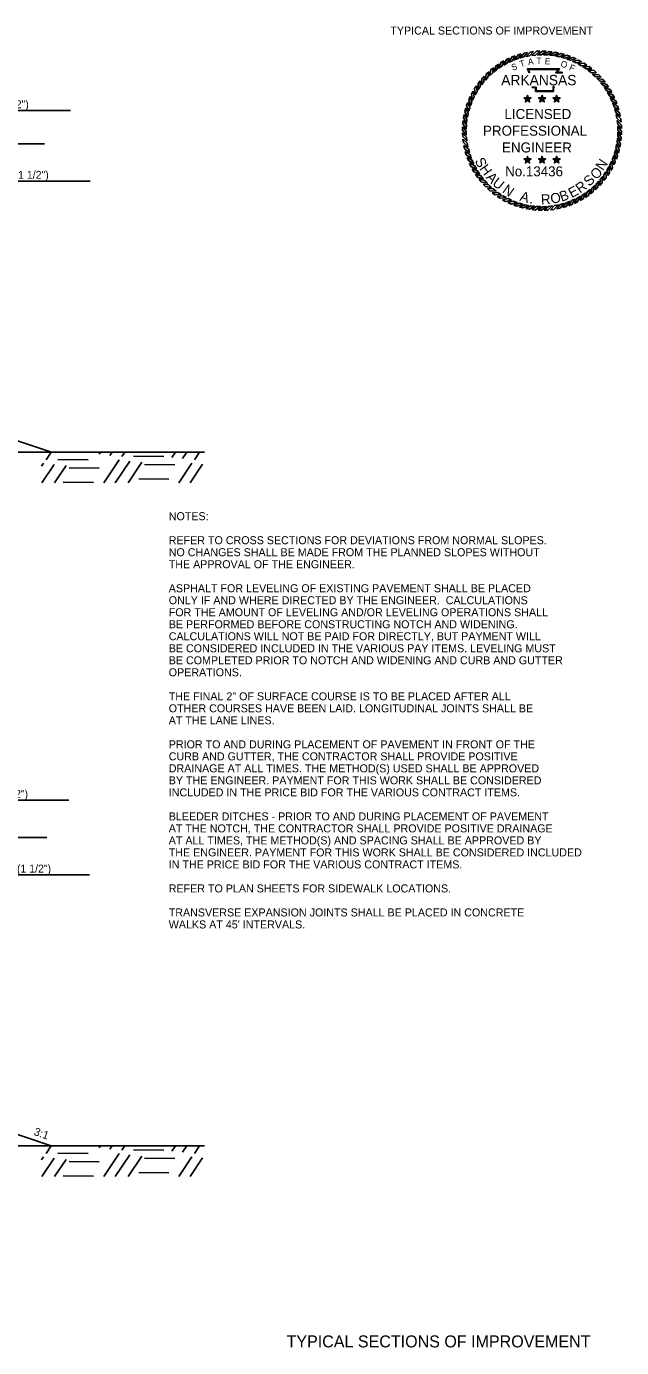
# Model space of a CAD drawing. Extents: x 1001270 to 1003428, y 1840152 to 1842912.
# Drawn here: x 1001904.5 to 1001949.2, y 1841962.9 to 1842061.9 of the extents above; entities that cross this region are included whole.
import ezdxf

# ---------------------------------------------------------------- set-up
doc = ezdxf.new("R2010")
doc.units = 0
for name, color, linetype in [('1', 7, 'Continuous'), ('19', 7, 'Continuous'), ('60', 7, 'Continuous'), ('G-ANNO-SYMB', 7, 'Continuous')]:
    doc.layers.add(name, color=color, linetype=linetype)

msp = doc.modelspace()

# ---------------------------------------------------------------- linework, layer by layer
at = {"layer": '19'}
for p, q in [((1001891.195, 1842055.58), (1001907.836, 1842055.58)), ((1001891.195, 1842053.086), (1001905.889, 1842053.086)), ((1001893.694, 1842050.286), (1001909.309, 1842050.286)), ((1001905.996, 1842029.386), (1001906.388, 1842029.969)), ((1001909.982, 1842029.82), (1001910.087, 1842029.97)), ((1001910.776, 1842029.729), (1001910.942, 1842029.973)), ((1001911.672, 1842029.636), (1001911.897, 1842029.975)), ((1001912.559, 1842029.666), (1001914.82, 1842029.654)), ((1001915.436, 1842029.581), (1001915.698, 1842029.976)), ((1001916.23, 1842029.489), (1001916.562, 1842029.978)), ((1001917.126, 1842029.397), (1001917.507, 1842029.971)), ((1001905.657, 1842028.918), (1001905.81, 1842029.144)), ((1001905.679, 1842027.67), (1001906.605, 1842029.052)), ((1001906.634, 1842027.672), (1001907.5, 1842028.96)), ((1001906.885, 1842029.425), (1001909.145, 1842029.404)), ((1001907.725, 1842028.796), (1001909.985, 1842028.775)), ((1001910.334, 1842027.673), (1001911.486, 1842029.394)), ((1001911.188, 1842027.676), (1001912.281, 1842029.302)), ((1001912.144, 1842027.678), (1001913.176, 1842029.21)), ((1001913.389, 1842029.037), (1001915.66, 1842029.025)), ((1001915.944, 1842027.679), (1001916.94, 1842029.155)), ((1001916.798, 1842027.681), (1001917.735, 1842029.063)), ((1001907.272, 1842027.717), (1001909.543, 1842027.704)), ((1001912.947, 1842027.967), (1001915.207, 1842027.946)), ((1001891.195, 1842003.888), (1001907.696, 1842003.888)), ((1001891.195, 1842001.088), (1001906.057, 1842001.088)), ((1001893.694, 1841998.288), (1001909.258, 1841998.288)), ((1001906.388, 1841977.971), (1001897.697, 1841980.868)), ((1001905.996, 1841977.388), (1001906.388, 1841977.971)), ((1001909.982, 1841977.822), (1001910.087, 1841977.972)), ((1001910.776, 1841977.73), (1001910.942, 1841977.975)), ((1001911.672, 1841977.638), (1001911.897, 1841977.977)), ((1001915.436, 1841977.583), (1001915.698, 1841977.978)), ((1001916.23, 1841977.491), (1001916.562, 1841977.979)), ((1001917.126, 1841977.399), (1001917.507, 1841977.973)), ((1001905.657, 1841976.92), (1001905.81, 1841977.146)), ((1001905.679, 1841975.671), (1001906.605, 1841977.054)), ((1001906.634, 1841975.674), (1001907.5, 1841976.962)), ((1001906.885, 1841977.427), (1001909.145, 1841977.406)), ((1001910.334, 1841975.675), (1001911.486, 1841977.396)), ((1001911.188, 1841975.677), (1001912.281, 1841977.304)), ((1001912.144, 1841975.68), (1001913.176, 1841977.212)), ((1001912.559, 1841977.668), (1001914.82, 1841977.656)), ((1001913.389, 1841977.039), (1001915.66, 1841977.027)), ((1001915.944, 1841975.681), (1001916.94, 1841977.156)), ((1001916.798, 1841975.683), (1001917.735, 1841977.065)), ((1001907.725, 1841976.798), (1001909.985, 1841976.776)), ((1001907.272, 1841975.719), (1001909.543, 1841975.706)), ((1001912.947, 1841975.969), (1001915.207, 1841975.947))]:
    msp.add_line(p, q, dxfattribs=at)
for points in [[(1001906.395, 1842029.969), (1001897.704, 1842032.866), (1001889.707, 1842032.706)], [(1001887.878, 1842031.719), (1001896.643, 1842030.165), (1001897.635, 1842029.97), (1001917.886, 1842029.968)], [(1001887.878, 1841979.721), (1001896.643, 1841978.167), (1001897.635, 1841977.972), (1001917.886, 1841977.97)]]:
    msp.add_lwpolyline(points, dxfattribs=at)
at = {"layer": 'G-ANNO-SYMB'}
for points in [[(1001940.336, 1842059.301), (1001940.114, 1842059.173), (1001939.954, 1842058.744), (1001940.185, 1842058.897)], [(1001940.756, 1842059.509), (1001940.524, 1842059.399), (1001940.331, 1842058.984), (1001940.574, 1842059.118)], [(1001941.191, 1842059.683), (1001940.951, 1842059.592), (1001940.726, 1842059.194), (1001940.978, 1842059.308)], [(1001941.638, 1842059.823), (1001941.392, 1842059.751), (1001941.136, 1842059.372), (1001941.397, 1842059.466)], [(1001942.094, 1842059.928), (1001941.843, 1842059.875), (1001941.559, 1842059.517), (1001941.826, 1842059.59)], [(1001942.558, 1842059.996), (1001942.303, 1842059.963), (1001941.992, 1842059.629), (1001942.264, 1842059.681)], [(1001943.025, 1842060.028), (1001942.769, 1842060.015), (1001942.432, 1842059.706), (1001942.707, 1842059.737)], [(1001943.494, 1842060.023), (1001943.237, 1842060.03), (1001942.877, 1842059.749), (1001943.154, 1842059.757)], [(1001943.96, 1842059.981), (1001943.705, 1842060.009), (1001943.324, 1842059.756), (1001943.601, 1842059.743)], [(1001944.422, 1842059.903), (1001944.17, 1842059.95), (1001943.77, 1842059.729), (1001944.045, 1842059.694)], [(1001944.876, 1842059.789), (1001944.629, 1842059.856), (1001944.213, 1842059.666), (1001944.484, 1842059.61)], [(1001945.32, 1842059.639), (1001945.079, 1842059.725), (1001944.649, 1842059.569), (1001944.915, 1842059.492)], [(1001945.751, 1842059.455), (1001945.517, 1842059.56), (1001945.076, 1842059.438), (1001945.336, 1842059.34)], [(1001946.166, 1842059.238), (1001945.941, 1842059.361), (1001945.492, 1842059.274), (1001945.743, 1842059.156)], [(1001939.193, 1842058.488), (1001939.007, 1842058.312), (1001938.951, 1842057.858), (1001939.141, 1842058.06)], [(1001939.553, 1842058.789), (1001939.353, 1842058.628), (1001939.262, 1842058.18), (1001939.467, 1842058.366)], [(1001939.934, 1842059.06), (1001939.723, 1842058.915), (1001939.597, 1842058.476), (1001939.816, 1842058.646)], [(1001946.563, 1842058.989), (1001946.348, 1842059.129), (1001945.894, 1842059.078), (1001946.135, 1842058.94)], [(1001946.939, 1842058.71), (1001946.736, 1842058.866), (1001946.279, 1842058.851), (1001946.508, 1842058.695)], [(1001947.292, 1842058.402), (1001947.102, 1842058.574), (1001946.645, 1842058.594), (1001946.861, 1842058.421)], [(1001947.62, 1842058.067), (1001947.444, 1842058.254), (1001946.99, 1842058.309), (1001947.192, 1842058.12)], [(1001938.271, 1842057.432), (1001938.131, 1842057.217), (1001938.182, 1842056.763), (1001938.32, 1842057.003)], [(1001938.55, 1842057.808), (1001938.394, 1842057.605), (1001938.41, 1842057.148), (1001938.565, 1842057.377)], [(1001938.858, 1842058.161), (1001938.686, 1842057.97), (1001938.666, 1842057.514), (1001938.84, 1842057.73)], [(1001947.92, 1842057.708), (1001947.759, 1842057.907), (1001947.311, 1842057.999), (1001947.498, 1842057.794)], [(1001948.191, 1842057.326), (1001948.047, 1842057.537), (1001947.607, 1842057.664), (1001947.777, 1842057.445)], [(1001948.432, 1842056.924), (1001948.304, 1842057.146), (1001947.876, 1842057.306), (1001948.028, 1842057.075)], [(1001937.621, 1842056.189), (1001937.535, 1842055.947), (1001937.691, 1842055.518), (1001937.768, 1842055.784)], [(1001937.805, 1842056.62), (1001937.7, 1842056.386), (1001937.822, 1842055.945), (1001937.92, 1842056.204)], [(1001938.022, 1842057.035), (1001937.899, 1842056.81), (1001937.986, 1842056.361), (1001938.104, 1842056.612)], [(1001942.105, 1842056.44), (1001942.044, 1842056.524), (1001941.845, 1842056.524), (1001942.006, 1842056.408)], [(1001942.105, 1842056.44), (1001942.006, 1842056.408), (1001941.945, 1842056.219), (1001942.105, 1842056.336)], [(1001942.105, 1842056.44), (1001942.166, 1842056.524), (1001942.105, 1842056.713), (1001942.044, 1842056.524)], [(1001942.105, 1842056.44), (1001942.204, 1842056.408), (1001942.364, 1842056.524), (1001942.166, 1842056.524)], [(1001942.105, 1842056.44), (1001942.105, 1842056.336), (1001942.265, 1842056.219), (1001942.204, 1842056.408)], [(1001943.196, 1842056.44), (1001943.135, 1842056.524), (1001942.936, 1842056.524), (1001943.097, 1842056.408)], [(1001943.196, 1842056.44), (1001943.097, 1842056.408), (1001943.035, 1842056.219), (1001943.196, 1842056.336)], [(1001943.196, 1842056.44), (1001943.257, 1842056.524), (1001943.196, 1842056.713), (1001943.135, 1842056.524)], [(1001943.196, 1842056.44), (1001943.295, 1842056.408), (1001943.455, 1842056.524), (1001943.257, 1842056.524)], [(1001943.196, 1842056.44), (1001943.196, 1842056.336), (1001943.356, 1842056.219), (1001943.295, 1842056.408)], [(1001944.287, 1842056.44), (1001944.225, 1842056.524), (1001944.027, 1842056.524), (1001944.188, 1842056.408)], [(1001944.287, 1842056.44), (1001944.188, 1842056.408), (1001944.126, 1842056.219), (1001944.287, 1842056.336)], [(1001944.287, 1842056.44), (1001944.348, 1842056.524), (1001944.287, 1842056.713), (1001944.225, 1842056.524)], [(1001944.287, 1842056.44), (1001944.386, 1842056.408), (1001944.546, 1842056.524), (1001944.348, 1842056.524)], [(1001944.287, 1842056.44), (1001944.287, 1842056.336), (1001944.447, 1842056.219), (1001944.386, 1842056.408)], [(1001948.64, 1842056.504), (1001948.53, 1842056.736), (1001948.116, 1842056.929), (1001948.249, 1842056.686)], [(1001948.815, 1842056.069), (1001948.723, 1842056.309), (1001948.325, 1842056.534), (1001948.439, 1842056.282)], [(1001937.357, 1842055.291), (1001937.31, 1842055.039), (1001937.532, 1842054.639), (1001937.566, 1842054.914)], [(1001937.471, 1842055.745), (1001937.404, 1842055.497), (1001937.594, 1842055.081), (1001937.65, 1842055.353)], [(1001948.955, 1842055.622), (1001948.882, 1842055.869), (1001948.503, 1842056.124), (1001948.597, 1842055.863)], [(1001949.059, 1842055.166), (1001949.006, 1842055.417), (1001948.649, 1842055.701), (1001948.722, 1842055.434)], [(1001949.127, 1842054.702), (1001949.095, 1842054.957), (1001948.76, 1842055.269), (1001948.812, 1842054.996)], [(1001937.237, 1842054.362), (1001937.23, 1842054.106), (1001937.511, 1842053.746), (1001937.503, 1842054.023)], [(1001937.279, 1842054.829), (1001937.252, 1842054.574), (1001937.504, 1842054.193), (1001937.517, 1842054.469)], [(1001949.159, 1842054.235), (1001949.146, 1842054.491), (1001948.837, 1842054.828), (1001948.868, 1842054.553)], [(1001949.154, 1842053.767), (1001949.162, 1842054.023), (1001948.88, 1842054.383), (1001948.889, 1842054.106)], [(1001937.232, 1842053.894), (1001937.245, 1842053.638), (1001937.554, 1842053.301), (1001937.524, 1842053.576)], [(1001937.264, 1842053.427), (1001937.297, 1842053.172), (1001937.631, 1842052.86), (1001937.579, 1842053.132)], [(1001949.034, 1842052.838), (1001949.082, 1842053.09), (1001948.86, 1842053.49), (1001948.825, 1842053.215)], [(1001949.113, 1842053.3), (1001949.14, 1842053.555), (1001948.888, 1842053.936), (1001948.875, 1842053.659)], [(1001937.332, 1842052.963), (1001937.385, 1842052.712), (1001937.743, 1842052.427), (1001937.67, 1842052.695)], [(1001937.437, 1842052.506), (1001937.509, 1842052.26), (1001937.888, 1842052.005), (1001937.794, 1842052.265)], [(1001948.771, 1842051.94), (1001948.857, 1842052.181), (1001948.7, 1842052.611), (1001948.623, 1842052.345)], [(1001948.92, 1842052.384), (1001948.987, 1842052.631), (1001948.797, 1842053.048), (1001948.741, 1842052.776)], [(1001937.577, 1842052.059), (1001937.668, 1842051.82), (1001938.066, 1842051.595), (1001937.952, 1842051.847)], [(1001937.751, 1842051.625), (1001937.861, 1842051.393), (1001938.276, 1842051.2), (1001938.142, 1842051.443)], [(1001942.105, 1842051.872), (1001942.044, 1842051.956), (1001941.845, 1842051.956), (1001942.006, 1842051.84)], [(1001942.105, 1842051.872), (1001942.006, 1842051.84), (1001941.945, 1842051.651), (1001942.105, 1842051.768)], [(1001942.105, 1842051.872), (1001942.166, 1842051.956), (1001942.105, 1842052.145), (1001942.044, 1842051.956)], [(1001942.105, 1842051.872), (1001942.204, 1842051.84), (1001942.364, 1842051.956), (1001942.166, 1842051.956)], [(1001942.105, 1842051.872), (1001942.105, 1842051.768), (1001942.265, 1842051.651), (1001942.204, 1842051.84)], [(1001943.196, 1842051.872), (1001943.135, 1842051.956), (1001942.936, 1842051.956), (1001943.097, 1842051.84)], [(1001943.196, 1842051.872), (1001943.097, 1842051.84), (1001943.035, 1842051.651), (1001943.196, 1842051.768)], [(1001943.196, 1842051.872), (1001943.257, 1842051.956), (1001943.196, 1842052.145), (1001943.135, 1842051.956)], [(1001943.196, 1842051.872), (1001943.295, 1842051.84), (1001943.455, 1842051.956), (1001943.257, 1842051.956)], [(1001943.196, 1842051.872), (1001943.196, 1842051.768), (1001943.356, 1842051.651), (1001943.295, 1842051.84)], [(1001944.287, 1842051.872), (1001944.225, 1842051.956), (1001944.027, 1842051.956), (1001944.188, 1842051.84)], [(1001944.287, 1842051.872), (1001944.188, 1842051.84), (1001944.126, 1842051.651), (1001944.287, 1842051.768)], [(1001944.287, 1842051.872), (1001944.348, 1842051.956), (1001944.287, 1842052.145), (1001944.225, 1842051.956)], [(1001944.287, 1842051.872), (1001944.386, 1842051.84), (1001944.546, 1842051.956), (1001944.348, 1842051.956)], [(1001944.287, 1842051.872), (1001944.287, 1842051.768), (1001944.447, 1842051.651), (1001944.386, 1842051.84)], [(1001948.121, 1842050.697), (1001948.261, 1842050.912), (1001948.209, 1842051.366), (1001948.072, 1842051.125)], [(1001948.37, 1842051.094), (1001948.492, 1842051.319), (1001948.405, 1842051.768), (1001948.287, 1842051.517)], [(1001948.587, 1842051.509), (1001948.692, 1842051.743), (1001948.569, 1842052.184), (1001948.471, 1842051.924)], [(1001937.96, 1842051.205), (1001938.087, 1842050.983), (1001938.516, 1842050.822), (1001938.363, 1842051.054)], [(1001938.2, 1842050.803), (1001938.345, 1842050.591), (1001938.785, 1842050.465), (1001938.615, 1842050.684)], [(1001938.471, 1842050.421), (1001938.632, 1842050.221), (1001939.08, 1842050.13), (1001938.894, 1842050.335)], [(1001947.198, 1842049.64), (1001947.385, 1842049.817), (1001947.441, 1842050.27), (1001947.251, 1842050.068)], [(1001947.533, 1842049.968), (1001947.705, 1842050.158), (1001947.725, 1842050.615), (1001947.552, 1842050.399)], [(1001947.841, 1842050.321), (1001947.998, 1842050.524), (1001947.982, 1842050.981), (1001947.826, 1842050.752)], [(1001938.772, 1842050.062), (1001938.948, 1842049.875), (1001939.402, 1842049.82), (1001939.2, 1842050.009)], [(1001939.099, 1842049.727), (1001939.29, 1842049.555), (1001939.747, 1842049.535), (1001939.53, 1842049.708)], [(1001939.452, 1842049.419), (1001939.656, 1842049.262), (1001940.113, 1842049.278), (1001939.883, 1842049.434)], [(1001946.055, 1842048.828), (1001946.278, 1842048.956), (1001946.438, 1842049.384), (1001946.206, 1842049.232)], [(1001946.457, 1842049.069), (1001946.669, 1842049.214), (1001946.795, 1842049.653), (1001946.576, 1842049.483)], [(1001946.839, 1842049.34), (1001947.039, 1842049.501), (1001947.13, 1842049.949), (1001946.925, 1842049.763)], [(1001939.828, 1842049.14), (1001940.043, 1842048.999), (1001940.498, 1842049.051), (1001940.257, 1842049.188)], [(1001940.225, 1842048.891), (1001940.45, 1842048.768), (1001940.899, 1842048.855), (1001940.648, 1842048.973)], [(1001940.64, 1842048.673), (1001940.874, 1842048.569), (1001941.315, 1842048.691), (1001941.056, 1842048.789)], [(1001941.071, 1842048.49), (1001941.313, 1842048.403), (1001941.742, 1842048.56), (1001941.476, 1842048.637)], [(1001941.515, 1842048.34), (1001941.763, 1842048.273), (1001942.179, 1842048.463), (1001941.907, 1842048.519)], [(1001941.969, 1842048.226), (1001942.222, 1842048.179), (1001942.621, 1842048.4), (1001942.346, 1842048.435)], [(1001942.431, 1842048.148), (1001942.686, 1842048.12), (1001943.068, 1842048.373), (1001942.791, 1842048.386)], [(1001942.898, 1842048.106), (1001943.154, 1842048.099), (1001943.515, 1842048.38), (1001943.238, 1842048.371)], [(1001943.366, 1842048.101), (1001943.622, 1842048.114), (1001943.96, 1842048.423), (1001943.684, 1842048.392)], [(1001943.834, 1842048.133), (1001944.088, 1842048.166), (1001944.4, 1842048.5), (1001944.128, 1842048.448)], [(1001944.297, 1842048.201), (1001944.548, 1842048.254), (1001944.833, 1842048.612), (1001944.565, 1842048.538)], [(1001944.754, 1842048.305), (1001945, 1842048.378), (1001945.256, 1842048.757), (1001944.995, 1842048.663)], [(1001945.201, 1842048.445), (1001945.44, 1842048.537), (1001945.666, 1842048.935), (1001945.413, 1842048.821)], [(1001945.635, 1842048.62), (1001945.867, 1842048.73), (1001946.06, 1842049.144), (1001945.818, 1842049.011)]]:
    msp.add_lwpolyline(points, close=True, dxfattribs=at)
for points in [[(1001942.24, 1842058.394), (1001942.101, 1842058.696), (1001944.507, 1842058.697), (1001944.306, 1842058.444), (1001944.47, 1842058.447), (1001944.606, 1842058.448), (1001944.743, 1842058.433)], [(1001942.275, 1842058.41), (1001942.16, 1842058.657), (1001944.428, 1842058.659), (1001944.226, 1842058.405), (1001944.47, 1842058.408), (1001944.604, 1842058.41), (1001944.739, 1842058.396)], [(1001944.128, 1842057.386), (1001944.087, 1842057.353), (1001944.073, 1842057.303), (1001944.06, 1842057.178), (1001944.06, 1842057.012), (1001942.716, 1842057.012), (1001942.716, 1842057.236), (1001942.716, 1842057.286), (1001942.662, 1842057.303), (1001942.471, 1842057.303), (1001942.437, 1842057.354)], [(1001944.104, 1842057.416), (1001944.053, 1842057.374), (1001944.036, 1842057.31), (1001944.022, 1842057.18), (1001944.022, 1842057.05), (1001942.755, 1842057.05), (1001942.755, 1842057.236), (1001942.755, 1842057.314), (1001942.668, 1842057.341), (1001942.491, 1842057.341), (1001942.469, 1842057.375)]]:
    msp.add_lwpolyline(points, dxfattribs=at)

# ---------------------------------------------------------------- texts
at = {"layer": '1'}
msp.add_text('TYPICAL SECTIONS OF IMPROVEMENT', height=0.6, dxfattribs=at).set_placement((1001931.816, 1842061.273))
at = {"layer": '19'}
for s, height, p in [('7\'-0" AVG. ACHM SURFACE COURSE (1/2")', 0.59001, (1001888.778, 1842055.754)), ('9\'-6" AVG. ACHM BASE COURSE (1 1/2")', 0.59001, (1001891.281, 1842050.461)), ('NOTES:', 0.6, (1001915.198, 1842024.869)), ('REFER TO CROSS SECTIONS FOR DEVIATIONS FROM NORMAL SLOPES.', 0.6, (1001915.198, 1842023.069)), ('NO CHANGES SHALL BE MADE FROM THE PLANNED SLOPES WITHOUT', 0.6, (1001915.198, 1842022.169)), ('THE APPROVAL OF THE ENGINEER.', 0.6, (1001915.198, 1842021.269)), ('ASPHALT FOR LEVELING OF EXISTING PAVEMENT SHALL BE PLACED', 0.6, (1001915.198, 1842019.469)), ('ONLY IF AND WHERE DIRECTED BY THE ENGINEER.  CALCULATIONS', 0.6, (1001915.198, 1842018.569)), ('FOR THE AMOUNT OF LEVELING AND/OR LEVELING OPERATIONS SHALL', 0.6, (1001915.198, 1842017.669)), ('BE PERFORMED BEFORE CONSTRUCTING NOTCH AND WIDENING.', 0.6, (1001915.198, 1842016.769)), ('CALCULATIONS WILL NOT BE PAID FOR DIRECTLY, BUT PAYMENT WILL', 0.6, (1001915.198, 1842015.869)), ('BE CONSIDERED INCLUDED IN THE VARIOUS PAY ITEMS. LEVELING MUST ', 0.6, (1001915.198, 1842014.969)), ('BE COMPLETED PRIOR TO NOTCH AND WIDENING AND CURB AND GUTTER', 0.6, (1001915.198, 1842014.069)), ('OPERATIONS. ', 0.6, (1001915.198, 1842013.169)), ('THE FINAL 2" OF SURFACE COURSE IS TO BE PLACED AFTER ALL', 0.6, (1001915.198, 1842011.369)), ('OTHER COURSES HAVE BEEN LAID. LONGITUDINAL JOINTS SHALL BE', 0.6, (1001915.198, 1842010.469)), ('AT THE LANE LINES.', 0.6, (1001915.198, 1842009.569)), ('PRIOR TO AND DURING PLACEMENT OF PAVEMENT IN FRONT OF THE', 0.6, (1001915.198, 1842007.769)), ('CURB AND GUTTER, THE CONTRACTOR SHALL PROVIDE POSITIVE', 0.6, (1001915.198, 1842006.869)), ('DRAINAGE AT ALL TIMES. THE METHOD(S) USED SHALL BE APPROVED', 0.6, (1001915.198, 1842005.969)), ('BY THE ENGINEER. PAYMENT FOR THIS WORK SHALL BE CONSIDERED', 0.6, (1001915.198, 1842005.069)), ('INCLUDED IN THE PRICE BID FOR THE VARIOUS CONTRACT ITEMS.', 0.6, (1001915.198, 1842004.169)), ('7\'-0" AVG. ACHM SURFACE COURSE (1/2")', 0.59001, (1001888.727, 1842004.062)), ('BLEEDER DITCHES - PRIOR TO AND DURING PLACEMENT OF PAVEMENT', 0.6, (1001915.198, 1842002.369)), ('AT THE NOTCH, THE CONTRACTOR SHALL PROVIDE POSITIVE DRAINAGE', 0.6, (1001915.198, 1842001.469)), ('AT ALL TIMES, THE METHOD(S) AND SPACING SHALL BE APPROVED BY', 0.6, (1001915.198, 1842000.569)), ('THE ENGINEER. PAYMENT FOR THIS WORK SHALL BE CONSIDERED INCLUDED', 0.6, (1001915.198, 1841999.669)), ('9\'-6" AVG. ACHM BASE COURSE (1 1/2")', 0.59001, (1001891.458, 1841998.462)), ('IN THE PRICE BID FOR THE VARIOUS CONTRACT ITEMS.', 0.6, (1001915.198, 1841998.769)), ('REFER TO PLAN SHEETS FOR SIDEWALK LOCATIONS.', 0.6, (1001915.198, 1841996.969)), ('TRANSVERSE EXPANSION JOINTS SHALL BE PLACED IN CONCRETE', 0.6, (1001915.198, 1841995.169)), ("WALKS AT 45' INTERVALS.", 0.6, (1001915.198, 1841994.269))]:
    msp.add_text(s, height=height, dxfattribs=at).set_placement(p)
msp.add_text('3:1', height=0.6, rotation=340.49426, dxfattribs=at).set_placement((1001905.031, 1841978.805))
at = {"layer": '60'}
msp.add_text('TYPICAL SECTIONS OF IMPROVEMENT', height=0.9, dxfattribs=at).set_placement((1001924.032, 1841962.865))
at = {"layer": 'G-ANNO-SYMB'}
for s, height, rotation, p in [('T', 0.475, 16.90148, (1001941.59, 1842058.823)), ('A', 0.475, 8.67877, (1001942.167, 1842058.974)), ('T', 0.475, 1.47887, (1001942.78, 1842059.068)), ('E', 0.475, 356.67203, (1001943.387, 1842059.054)), ('O', 0.475, 341.2218, (1001944.54, 1842058.891)), ('ARKANSAS', 0.7747, 360, (1001940.134, 1842057.473)), ('S', 0.475, 19.77256, (1001940.987, 1842058.552)), ('F', 0.475, 335.36282, (1001945.179, 1842058.641)), ('LICENSED', 0.75, 360, (1001940.374, 1842054.944)), ('PROFESSIONAL', 0.75, 360, (1001938.767, 1842053.689)), ('ENGINEER', 0.75, 360, (1001940.196, 1842052.435)), ('S', 0.75, 298.16364, (1001938.128, 1842051.805)), ('H', 0.75, 305.61905, (1001938.47, 1842051.217)), ('No.13436', 0.747, 360, (1001940.432, 1842050.647)), ('O', 0.75, 44.77573, (1001947.249, 1842050.346)), ('N', 0.75, 56.10067, (1001947.77, 1842051.021)), ('A', 0.75, 313.44722, (1001938.946, 1842050.532)), ('U', 0.75, 320.90262, (1001939.413, 1842050.043)), ('R', 0.75, 35.65967, (1001946.044, 1842049.338)), ('S', 0.75, 43.48784, (1001946.734, 1842049.848)), ('N', 0.75, 324.93262, (1001940.169, 1842049.485)), ('A', 0.75, 343.09908, (1001941.477, 1842048.841)), ('R', 0.75, 3.22866, (1001943.133, 1842048.528)), ('O', 0.75, 11.42961, (1001943.901, 1842048.576)), ('B', 0.75, 18.88501, (1001944.653, 1842048.735)), ('E', 0.75, 27.83149, (1001945.41, 1842049.006)), ('.', 0.75, 351.30002, (1001942.214, 1842048.623))]:
    msp.add_text(s, height=height, rotation=rotation, dxfattribs=at).set_placement(p)

doc.saveas('drawing.dxf')
